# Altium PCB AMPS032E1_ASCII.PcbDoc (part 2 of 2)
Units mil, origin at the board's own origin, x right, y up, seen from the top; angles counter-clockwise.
Board outline 1650 x 2660 mil, 4 copper layers (Top Layer L1, GND Plane L2, VCC/VEE Plane L3, Bottom Layer L4), stack 61.6 mil thick; 53 components, 15 nets, 89 pads, 109 vias.
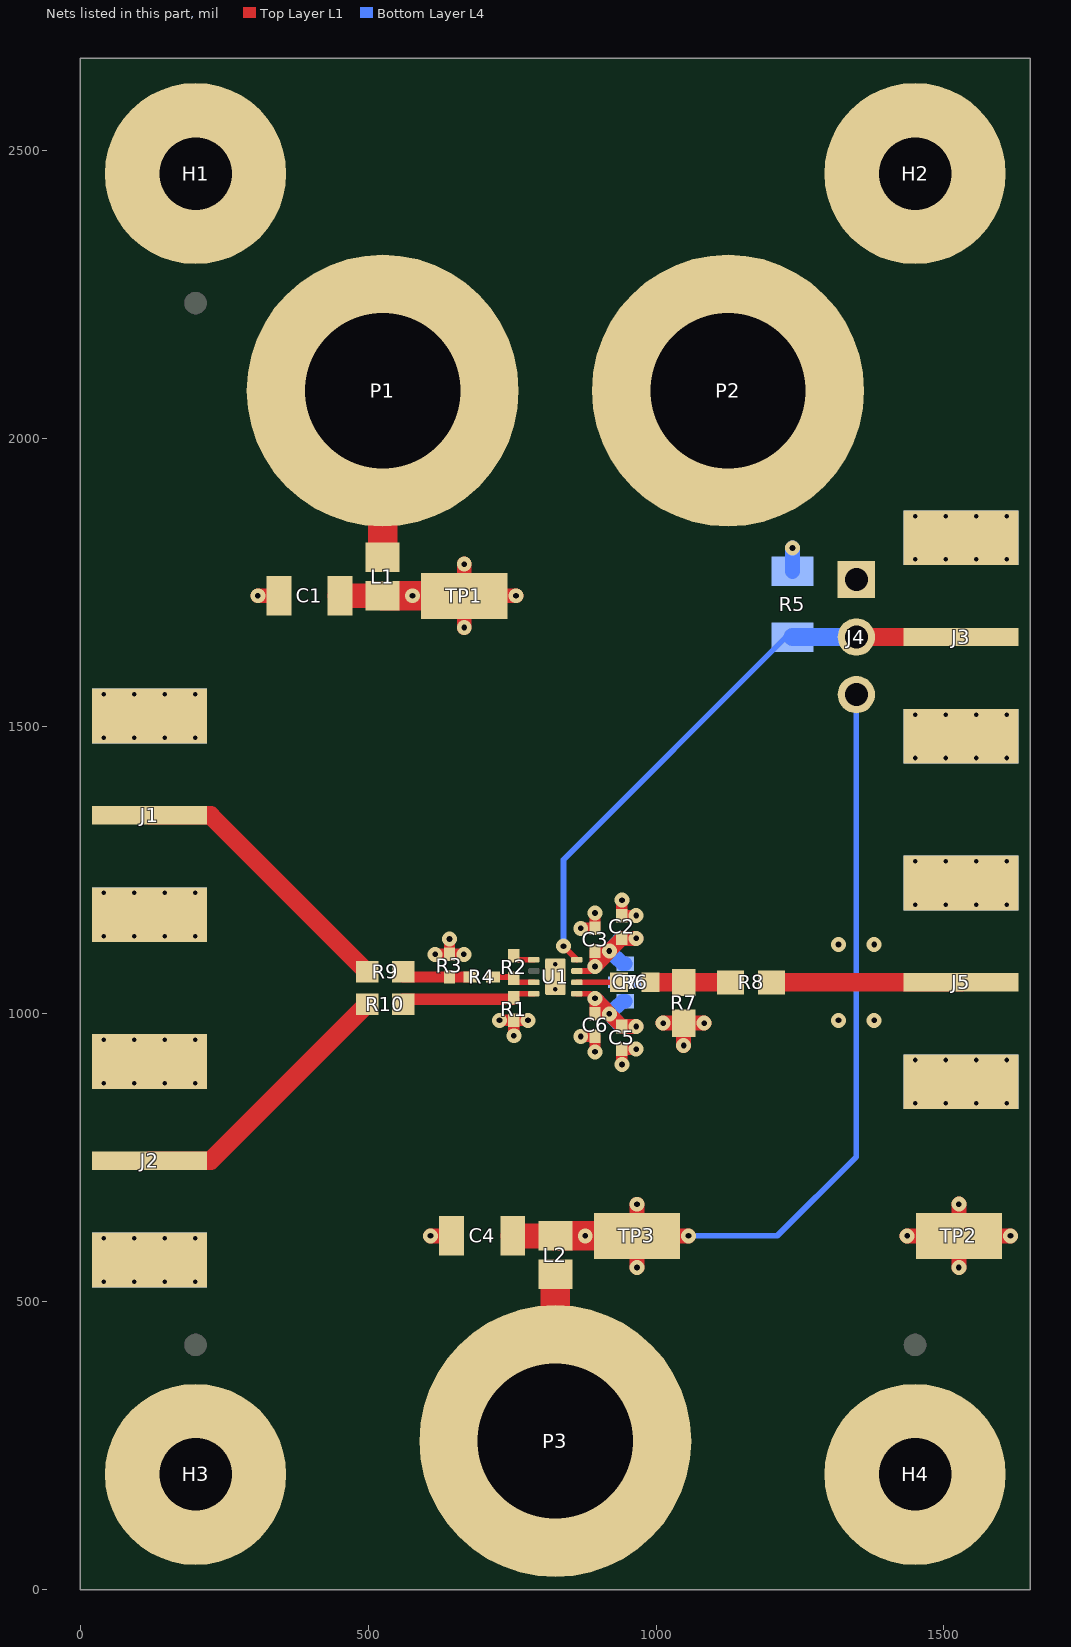
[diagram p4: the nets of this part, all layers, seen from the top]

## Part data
C1 C4: library part CMP-0008990-2, "CAP, CERM, 2.2 uF, 25 V, +/- 10%, X7R, 1206"
C2 C5: library part CMP-0006277-2, "CAP, CERM, 0.22 uF, 25 V, +/- 20%, X5R, 0402"
C3 C6: library part CMP-0006658-2, "CAP, CERM, 0.01 uF, 25 V, +/- 10%, X7R, 0402"
C7: library part CMP-0006820-2, "CAP, CERM, 0.01 uF, 50 V, +/- 20%, X7R, 0603"
FID1 FID2 FID3 FID4 FID5 FID6: "Fiducial mark.  There is nothing to buy or mount."
H1 H2 H3 H4: "Machine Screw, Round, #4-40 x 1/4, Nylon, Philips panhead"
H5 H6 H7 H8: "Standoff, Hex, 0.5\"L #4-40 Nylon"
J1 J2 J3 J5: library part CMP-0055822-1, "Connector, End launch SMA, 50 ohm, SMT"
J4: library part CMP-0075407-1, "Header, 100mil, 3x1, Gold, TH"
L1 L2: library part CMP-0003356-1, "Ferrite Bead, 1000 ohm @ 100 MHz, 0.5 A, 0805"
LBL1: library part THT-14-423-10, "Thermal Transfer Printable Labels, 0.650\" W x 0.200\" H - 10,000 per roll"
Logo1: library part TI_Logo, "Texas Instrument Corporate Signature"
Logo2: library part Pb-Free
Logo3: library part FCC_disclaimer, "FCC_disclaimer"
P1 P2 P3: library part CMP-0055169-2, "Standard Banana Jack, Uninsulated"
R1: library part CMP-0026404-1, "RES, 49.9, 1%, 0.063 W, 0402"
R2: library part CMP-0026366-1, "RES, 402, 1%, 0.063 W, 0402"
R3: library part CMP-0026822-2, "RES, 0, 5%, 0.063 W, 0402"
R4: library part CMP-0026503-1, "RES, 66.5, 1%, 0.063 W, 0402"
R5: library part CMP-0017019-2, "RES, 49.9, 1%, 0.25 W, 1206"
R6: library part CMP-0022078-3, "RES, 169, 1%, 0.1 W, 0603"
R7: library part CMP-0022582-2, "RES, 71.5, 1%, 0.1 W, 0603"
R8 R9 R10: library part CMP-0025697-2, "RES, 0, 5%, 0.1 W, 0603"
TP1 TP2 TP3: library part CMP-0055162-1, "Test Point, Miniature, SMT"
U1: library part CMP-0013445-3, "OPA852IDSG, DSG0008A (WSON-8)"
ZZ1: library part AssemblyNoteLabel
ZZ2 ZZ3 ZZ4: library part AssemblyNote

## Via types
v1: diameter 19.68, hole 7.87, Top Layer L1 to Bottom Layer L4, tented both sides, 64 vias
v2: diameter 26, hole 10, Top Layer L1 to Bottom Layer L4, tented both sides, 43 vias
v3: diameter 19.68, hole 7.87, Top Layer L1 to Bottom Layer L4, 2 vias

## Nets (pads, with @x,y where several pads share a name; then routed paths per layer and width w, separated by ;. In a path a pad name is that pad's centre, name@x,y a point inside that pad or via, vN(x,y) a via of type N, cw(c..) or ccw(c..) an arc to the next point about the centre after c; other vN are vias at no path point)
GND: C1.2 C2.2 C3.2 C4.1 C5.1 C6.1 C7.3 H1.1 H2.1 H3.1 H4.1 J1.2 J1.3 J1.4 J1.5 J2.2 J2.3 J2.4 J2.5 J3.2 J3.3 J3.4 J3.5 J5.2 J5.3 J5.4 J5.5 P2.1 R1.1 R3.1 R5.1 R7.1 TP2.1 | length 872.2
  Top Layer L1 w19.68: v2(616.31,1103.64) R3.1@641.12,1103.64 ; v2(641.12,1130.42) R3.1@641.12,1103.64 ; v2(665.93,1103.64) R3.1@641.12,1103.64 ; v2(728.07,988.9) R1.1@752.88,988.9 ; v2(752.88,962.12) R1.1@752.88,988.9 ; v2(777.69,988.9) R1.1@752.88,988.9 ; v2(869.19,960.93) C6.1@894,960.93 v2(894,934.15) ; v2(869.19,1148.76) C3.2@894,1148.76 v2(894,1175.53) ; v2(940.63,912.07) C5.1@940.63,938.84 v2(965.44,938.84) ; v2(940.63,1197.62) C2.2@940.63,1170.84 v2(965.44,1170.84)
  Top Layer L1 w26: v2(308.08,1726.53) C1.2@344.7,1726.53 ; v2(608.08,614.47) C4.1@644.7,614.47 ; v2(1012.36,983.98) R7.1@1048,983.98 ; v2(1048,945.39) R7.1@1048,983.98 ; v2(1083.64,983.98) R7.1@1048,983.98 ; v2(1436.23,614.47) TP2.1@1526,614.47 ; v2(1526,559.54) TP2.1@1526,614.47 ; v2(1526,669.39) TP2.1@1526,614.47 ; v2(1615.77,614.47) TP2.1@1526,614.47
  Bottom Layer L4 w26: R5.1@1237,1769.02 v2(1237,1809.57)
  other v1: 40.5,534.84 93.5,534.84 146.5,534.84 199.5,534.84 40.5,610.16 93.5,610.16 146.5,610.16 199.5,610.16 1450.5,844.68 1503.5,844.68 1556.5,844.68 1609.5,844.68 40.5,879.84 93.5,879.84 146.5,879.84 199.5,879.84 1450.5,920 1503.5,920 1556.5,920 1609.5,920 40.5,955.16 93.5,955.16 146.5,955.16 199.5,955.16 40.5,1134.84 93.5,1134.84 146.5,1134.84 199.5,1134.84 1450.5,1189.68 1503.5,1189.68 1556.5,1189.68 1609.5,1189.68 40.5,1210.16 93.5,1210.16 146.5,1210.16 199.5,1210.16 1450.5,1265 1503.5,1265 1556.5,1265 1609.5,1265 1450.5,1444.68 1503.5,1444.68 1556.5,1444.68 1609.5,1444.68 40.5,1479.84 93.5,1479.84 146.5,1479.84 199.5,1479.84 1450.5,1520 1503.5,1520 1556.5,1520 1609.5,1520 40.5,1555.16 93.5,1555.16 146.5,1555.16 199.5,1555.16 1450.5,1789.68 1503.5,1789.68 1556.5,1789.68 1609.5,1789.68 1450.5,1865 1503.5,1865 1556.5,1865 1609.5,1865
  other v2: 1317,989 1379,989 1317,1120.68 1379,1120.68
NetJ1_1: J1.1 R9.2 | length 490.6
  Top Layer L1 w32: J1.1@120,1345 226.14,1345 R9.2@498,1073.13
NetJ2_1: J2.1 R10.2 | length 490.6
  Top Layer L1 w32: J2.1@120,745 226.14,745 R10.2@498,1016.87
NetJ3_1: J3.1 J4.2 R5.2 U1.8 | length 1034.7
  Top Layer L1 w9.84: v2(839,1117.69) U1.8@862.44,1094.25
  Top Layer L1 w32: J4.2@1348,1654.84 J3.1@1530,1654.84
  Bottom Layer L4 w10: v2(839,1117.69) 839,1268 1225.84,1654.84 R5.2@1237,1654.84
  Bottom Layer L4 w32: R5.2@1237,1654.84 J4.2@1348,1654.84
NetJ5_1: J5.1 R8.2 | length 329.6
  Top Layer L1 w32: R8.2@1200.43,1054.84 J5.1@1530,1054.84
NetL1_1: L1.1 P1.1 | length 289.5
  Top Layer L1 w51.18: L1.1@525,1793.46 P1.1@525,2083
NetL2_1: L2.1 P3.1 | length 289.5
  Top Layer L1 w51.18: P3.1@825,258 L2.1@825,547.54
NetR1_2: R1.2 R10.1 U1.4 | length 238.3
  Top Layer L1 w9.84: R1.2@752.88,1028.27 759.77,1035.16 U1.4@787.6,1035.16
  Top Layer L1 w19.68: R10.1@561,1016.87 561,1025.73 R1.2@752.88,1025.73
NetR2_1: R2.1 R4.2 U1.3 | length 73.8
  Top Layer L1 w9.84: R4.2@716.69,1064.27 R2.1@752.88,1064.27 ; R2.1@752.88,1061.73 759.77,1054.84 U1.3@787.6,1054.84
NetR2_2: R2.2 U1.1 | length 37.6
  Top Layer L1 w9.84: R2.2@752.88,1101.1 759.77,1094.21 U1.1@787.6,1094.21
NetR3_2: R3.2 R4.1 R9.1 | length 125.2
  Top Layer L1 w19.68: R9.1@561,1073.13 561,1064.27 R3.2@641.12,1064.27 R4.1@677.32,1064.27
NetR6_1: R6.1 U1.6 | length 72.7
  Top Layer L1 w9.84: U1.6@862.4,1054.84 R6.1@935.15,1054.84
NetR6_2: R6.2 R7.2 R8.1 | length 139
  Top Layer L1 w32: R6.2@990.56,1054.84 R7.2@1048,1054.84 R8.1@1129.57,1054.84
VCC: C1.1 C2.1 C3.1 C7.2 J4.1 L1.2 TP1.1 U1.7 | length 723.1
  Top Layer L1 w9.84: U1.7@862.4,1074.53 885.92,1074.53 v2(894,1082.61)
  Top Layer L1 w19.68: v2(894,1082.61) C3.1@894,1109.39 v2(918.81,1109.39) ; C2.1@940.63,1131.2 C2.1@940.63,1131.47
  Top Layer L1 w26: v2(666.75,1671.61) TP1.1@666.75,1726.54 ; v2(666.75,1781.46) TP1.1@666.75,1726.54 ; v2(756.52,1726.54) TP1.1@666.75,1726.54 ; v2(894,1082.61) 907.35,1097.02 v2(918.81,1109.39) C2.1@940.63,1131.2 ; C2.1@940.63,1131.47 v2(965.44,1131.47)
  Top Layer L1 w43.31: C1.1@451,1726.53 L1.2@525,1726.54
  Top Layer L1 w51.18: L1.2@525,1726.54 TP1.1@666.75,1726.54
  Bottom Layer L4 w25.2: v2(918.81,1109.39) 941.76,1087.52 C7.2@946.5,1087.52
  Bottom Layer L4 w26: v2(894,1082.61) v2(918.81,1109.39) 938.31,1130.44 v2(965.44,1131.47)
  other v2: 576.98,1726.54
VEE: C4.2 C5.2 C6.2 C7.1 J4.3 L2.2 TP3.1 U1.5 U1.9@825,1064.68 | length 1874.4
  Top Layer L1 w9.84: U1.5@862.4,1035.16 885.92,1035.16 v2(894,1027.08)
  Top Layer L1 w19.68: v2(894,1027.08) C6.2@894,1000.3 v2(918.81,1000.3) ; C5.2@940.63,978.21 C5.2@940.63,978.48
  Top Layer L1 w26: v2(894,1027.08) 907.35,1012.67 v2(918.81,1000.3) C5.2@940.63,978.48 ; C5.2@940.63,978.21 v2(965.44,978.21) ; v2(966.75,559.54) TP3.1@966.75,614.46 ; v2(966.75,669.39) TP3.1@966.75,614.46 ; v2(1056.52,614.46) TP3.1@966.75,614.46
  Top Layer L1 w43.31: C4.2@751,614.47 L2.2@825,614.46
  Top Layer L1 w51.18: L2.2@825,614.46 TP3.1@966.75,614.46
  Bottom Layer L4 w10: v2(1056.52,614.46) 1210.46,614.46 1348,752 J4.3@1348,1554.84
  Bottom Layer L4 w25.2: v2(918.81,1000.3) 941.76,1022.17 C7.1@946.5,1022.17
  Bottom Layer L4 w26: v2(894,1027.08) v2(918.81,1000.3) 938.31,979.25 v2(965.44,978.21)
  other v2: 876.98,614.46
  other v3: 825,1043.03 825,1086.34
pads on no net: FID1.1 FID2.1 FID3.1 FID4.1 FID5.1 FID6.1 U1.2 U1.9@825,1046.97 U1.9@825,1082.4

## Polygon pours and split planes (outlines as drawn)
GND on Bottom Layer L4 "Bottom Layer L4-GND" (solid, remove dead copper, pour order 0): 20,20 20,2640 1630,2640 1630,20
GND on Top Layer L1 "Top Layer L1-GND" (solid, remove dead copper, pour order 2): 20,20 20,2640 1630,2640 1630,20
GND on GND Plane L2 (split plane): 1629.9,20.1 20.1,20.1 20.1,2639.9 1629.9,2639.9
VEE on VCC/VEE Plane L3 (split plane): 837.9,1054.84 838.29,1052.89 839.4,1051.24 841.05,1050.13 843,1049.74 847.87,1049.74 848.44,1048.38 849.56,1046.92 851.01,1045.8 852.71,1045.1 854.53,1044.86 914.69,1044.84 914.69,1033.11 956.19,1033.11 956.19,1049.74 1629.9,1049.74 1629.9,20.1 20.1,20.1 20.1,1039.9 807,1039.9 808.95,1040.29 810.6,1041.4 811.71,1043.05 812.1,1045 812.1,1106.03 837.9,1106.03
VCC on VCC/VEE Plane L3 (split plane): 1629.9,1059.94 956.19,1059.94 956.19,1076.57 914.69,1076.57 914.69,1064.85 854.53,1064.82 852.71,1064.58 851.01,1063.88 849.56,1062.76 848.44,1061.31 848.1,1060.48 848.1,1111.13 847.71,1113.08 846.61,1114.74 844.95,1115.84 843,1116.23 807,1116.23 805.05,1115.84 803.4,1114.74 802.29,1113.08 801.9,1111.13 801.9,1060.48 801.56,1061.31 800.44,1062.76 798.99,1063.88 797.29,1064.58 795.47,1064.82 787.79,1064.82 787.6,1064.85 767.72,1064.85 767.72,1078.54 738.04,1078.54 733.5,1079.12 699.87,1079.11 699.87,1050.1 20.1,1050.1 20.1,2639.9 1629.9,2639.9

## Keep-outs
Keep-Out Layer:
  text ".Layer_Name" at 577,-858.49 h60

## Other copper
Top Layer L1:
  text ".Layer_Name" at 577,-858.49 h60
Bottom Layer L4:
  text ".Layer_Name" at 577,-858.49 h60
GND Plane L2 (plane layer: these items are gaps in the copper):
  the board outline again, w40
  text ".Layer_Name" at 577,-858.49 h60
VCC/VEE Plane L3 (plane layer: these items are gaps in the copper):
  lines w10: 0,1045 807,1045 807,1111.13 843,1111.13 843,1054.84 1650,1054.84
  lines w40: 0,0 0,2660 1650,2660 1650,0 0,0
  text ".Layer_Name" at 577,-858.49 h60

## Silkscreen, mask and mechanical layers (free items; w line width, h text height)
Top Overlay:
  circle w10: c795.47,1133.13 r5
  text "HIGH" at 1133.41,1734.84 h40
  text "LOW" at 1166.41,1534.84 h40
  text "'.PRJ_Number'.PCB_Rev" at 275,432 h40
  text ".Layer_Name" at 577,-858.49 h60
Bottom Overlay:
  text ".Layer_Name" at 577,-858.49 h60
Top Paste:
  text ".Layer_Name" at 577,-858.49 h60
Bottom Paste:
  text ".Layer_Name" at 577,-858.49 h60
Top Solder:
  text ".Layer_Name" at 577,-858.49 h60
  text ".Layer_Name" at 577,-858.49 h60
Bottom Solder:
  text ".Layer_Name" at 577,-858.49 h60
Drill Guide:
  text ".Layer_Name" at 577,-858.49 h60
M1 Board Outline:
  the board outline again, w10
  text ".Layer_Name" at 577,-858.49 h60
M2 Board Dimensions:
  rectangle: 125,-400 500,-275
  rectangle: 0,-275 125,-150
  lines w7: 0,-275 1000,-275 ; 125,-400 125,-150 ; 250,-400 250,-150 ; 500,-400 500,-150 ; 750,-400 750,-150 ; 0,-400 0,-150 1000,-150 1000,-400 0,-400
  text ".Layer_Name" at 577,-858.49 h60
M3 3D STEP Top:
  text ".Layer_Name" at 577,-858.49 h60
M4 3D STEP Bottom:
  text ".Layer_Name" at 577,-858.49 h60
M5 Assembly Top:
  lines w10: -292,-930.17 6308,-930.17 ; -292,-726.83 6310,-726.83 ; -292,-523.5 -292,-1133.5 3713,-1133.5 6310,-1133.5 6310,-523.5 -291.5,-523.5 -291.5,-1133.5 1284,-1133.5 ; 2173,-1133.5 2173,-523.5 ; 3440,-726.83 3440,-523.5 ; 4280,-726.83 4280,-523.5 ; 4902,-1140 4902,-937.17
  text "COMPONENTS MARKED 'DNP' SHOULD NOT BE POPULATED." at 1153.5,-318.5 h60
  text "ASSEMBLY VARIANT:" at 1153,-434 h60
  text ".VariantName" at 2189,-434 h60
  text "PCB VIEWED FROM TOP SIDE" at -228.5,-655.67 h60
  text "BOARD #:" at 2248,-655.67 h60
  text ".PRJ_Number" at 2793.5,-655.67 h60
  text "REV:" at 3638,-655.67 h60
  text ".PCB_Rev" at 3929.5,-655.67 h60
  text "SVN REV:" at 4476,-655.67 h60
  text ".VersionControl_RevNumber" at 4982,-655.67 h60
  text "TID #:" at 2248,-859 h60
  text ".TID" at 2793.5,-859 h60
  text "PLOT NAME =" at -228.5,-1064.34 h60
  text ".plot_File_Name" at 577,-1064.34 h60
  text "GENERATED    :" at 2250,-1064.34 h60
  text ".Print_Date" at 3119.5,-1064.34 h60
  text ".Print_Time" at 3848.5,-1064.34 h60
  text "TEXAS INSTRUMENTS" at 5113,-1064.34 h60
M6 Assembly Bottom:
  lines w10: -292.5,-727.33 6309.5,-727.33 ; -290.5,-930.67 6309.5,-930.67 ; 1115.5,-1140.5 1115.5,-937.67 ; 1737.5,-727.33 1737.5,-524 ; 2577.5,-727.33 2577.5,-524 ; 3844.5,-1134 3844.5,-524 ; 4733.5,-1134 6309,-1134 6309,-524 -292.5,-524 -292.5,-1134 2304.5,-1134 6309.5,-1134 6309.5,-524
  text "COMPONENTS MARKED 'DNP' SHOULD NOT BE POPULATED." at 6102,-318 h60
  text ".VariantName" at 5058,-434 h60
  text "ASSEMBLY VARIANT:" at 6097,-434 h60
  text ".VersionControl_RevNumber" at 1035.5,-656.17 h60
  text "SVN REV:" at 1541.5,-656.17 h60
  text ".PCB_Rev" at 2088,-656.17 h60
  text "REV:" at 2379.5,-656.17 h60
  text ".PRJ_Number" at 3224,-656.17 h60
  text "BOARD #:" at 3769.5,-656.17 h60
  text "PCB VIEWED FROM BOTTOM SIDE" at 6246,-656.17 h60
  text ".TID" at 3224,-859.5 h60
  text "TID #:" at 3769.5,-859.5 h60
  text "TEXAS INSTRUMENTS" at 904.5,-1064.84 h60
  text ".Print_Time" at 2169,-1064.84 h60
  text ".Print_Date" at 2898,-1064.84 h60
  text "GENERATED    :" at 3767.5,-1064.84 h60
  text ".plot_File_Name" at 5440.5,-1064.84 h60
  text "PLOT NAME =" at 6246,-1064.84 h60
M9 Title Sheet:
  lines w10: -491.5,1041.5 -291.5,1041.5 ; -491.5,3416.5 -291.5,3416.5 ; -491.5,5791.5 -291.5,5791.5 ; 2008.5,-1333.5 2008.5,-1133.5 ; 2008.5,7966.5 2008.5,8166.5 ; 4508.5,-1333.5 4508.5,-1133.5 ; 4508.5,7966.5 4508.5,8166.5 ; 6321,-1133.5 6321,-523.5 11303.5,-523.5 ; 7008.5,-1333.5 7008.5,-1133.5 ; 7008.5,7966.5 7008.5,8166.5 ; 9508.5,-1333.5 9508.5,-1133.5 ; 9508.5,7966.5 9508.5,8166.5 ; 11303.5,-1133.5 11303.5,-523.5 ; 11303.5,-823.5 14303.5,-823.5 ; 11303.5,-223.5 14303.5,-223.5 ; 11304.5,370.5 14304.5,370.5 ; 12008.5,-1333.5 12008.5,-1133.5 ; 12008.5,7966.5 12008.5,8166.5 ; 12808.5,-1123.5 12808.5,-523.5 ; 14303.5,-523.5 11303.5,-523.5 ; 14303.5,76.5 11303.5,76.5 ; 14308.5,66.5 14308.5,-1133.5 ; 14308.5,871 11304.5,871 11303.5,871 11303.5,370.5 11303.5,76.5 ; 14308.5,1041.5 14508.5,1041.5 ; 14308.5,3416.5 14508.5,3416.5 ; 14308.5,5791.5 14508.5,5791.5 ; 11303.5,-523.5 11303.5,76.5 ; 14308.5,-1133.5 -291.5,-1133.5 -291.5,7966.5 14308.5,7966.5 14308.5,-1133.5 ; -491.5,-1333.5 14508.5,-1333.5 14508.5,8166.5 -491.5,8166.5 -491.5,-1333.5
  text "1" at 739.84,8036.5 h70
  text "2" at 3235.5,8036.5 h70
  text "3" at 5724.84,8036.5 h70
  text "4" at 8231.51,8036.5 h70
  text "5" at 10730.5,8036.5 h70
  text "6" at 13235.5,8036.5 h70
  text "A" at -416.5,6893.5 h70
  text "A" at 14383.5,6893.5 h70
  text "B" at -416.5,4513.5 h70
  text "B" at 14383.5,4513.5 h70
  text "C" at -416.5,2138.5 h70
  text "C" at 14383.5,2138.5 h70
  text "PROJECT TITLE:" at 11343.5,277.5 h45
  text ".PRJ_Title" at 11393.5,144.17 h70
  text "DESIGNED FOR:" at 11343.5,-23.5 h45
  text ".PRJ_Customer" at 11393.5,-163.5 h70
  text "D" at -416.5,-231.5 h70
  text "D" at 14383.5,-231.5 h70
  text "FILE NAME:" at 11343.5,-323.5 h45
  text ".PCB_File_Name_No_Path" at 11393.5,-443.5 h70
  text "Texas Instruments (TI) and/or its licensors do not warrant the accuracy or completeness of this specification" at 6374,-605.34 h45
  text "ENGINEER:" at 11343.5,-613.5 h45
  text "LAYOUT BY:" at 12848.5,-613.5 h45
  text "or any information contained therein. TI and/or its licensors do not warrant that this design will meet" at 6329.01,-718 h45
  text ".PRJ_Engineer" at 11393.5,-768.49 h70
  text ".PCB_Layout" at 12899,-768.49 h70
  text "the specifications, will be suitable for your application or fit for any particular purpose, or will operate in" at 6329.01,-830.67 h45
  text ".Layer_Name" at 577,-858.49 h60
  text "ALTIUM DESIGNER VERSION:" at 12848.5,-923.5 h45
  text "an implementation. TI and/or its licensors do not warrant that the design is production worthy. You should" at 6329.01,-943.33 h45
  text "completely validate and test your design implementation to confirm the system functionality for your application." at 6374,-1056 h45
  text ".print_Scale" at 11393.5,-1056.83 h70
  text ".Application_BuildNumber" at 12899,-1056.83 h70
  text "1" at 739.84,-1263.5 h70
  text "2" at 3235.5,-1263.5 h70
  text "3" at 5724.84,-1263.5 h70
  text "4" at 8231.51,-1263.5 h70
  text "5" at 10730.5,-1263.5 h70
  text "6" at 13235.5,-1263.5 h70
M10 Fab Notes:
  drawing of 173 lines, arcs and shapes, not listed
  text "DESIGN INFORMATION" at 12378.02,6201 h60
  text "MIN. TRACK WIDTH:" at 11733.46,6021 h60
  text "8" at 12829.7,6021 h60
  text "MIL" at 12984.46,6021 h60
  text "MIN. CLEARANCE:" at 11733.46,5889 h60
  text "0.2" at 12769.7,5889 h60
  text "mm" at 12984.46,5889 h60
  text "MIN. VIA PAD SIZE:" at 11733.46,5757 h60
  text "24" at 12799.71,5757 h60
  text "MIL" at 12984.46,5757 h60
  text "0.05mm (2MIL)" at 12428.46,5615.29 h60
  text "MINIMUM ANNULAR RING" at 11404.23,5611 h60
  text "EXTERNAL" at 13136.46,5611 h60
  text "PER" at 11604.23,5493 h60
  text "IPC-D-275 CLASS 2 LEVEL C" at 11824.23,5493 h60
  text "MIL, HOLES" at 13312.46,5380.71 h60
  text "+/-" at 12920,5380 h60
  text "+/-" at 13774,5380 h60
  text "REGISTRATION TOLERANCES:" at 11404.23,5375 h60
  text "METAL" at 12604,5375 h60
  text "5" at 13180.2,5375 h60
  text "3" at 14013.2,5375 h60
  text "MIL" at 14129.46,5375 h60
  text "+/-" at 13774,5262 h60
  text "HOLE SIZE TOLERANCE (UNLESS OTHERWISE SPECIFIED):" at 11404.23,5257 h60
  text "3" at 14013.2,5257 h60
  text "MIL" at 14129.46,5257 h60
  text "MATERIAL:" at 11329.46,5047.54 h60
  text "FR-4 High Tg" at 12315.9,4907.21 h60
  text "FR-408" at 11750.46,4898.64 h60
  text "OTHER" at 13238.46,4898.64 h60
  text "X" at 11602,4895 h60
  text "X" at 12161,4895 h60
  text "62 MIL (1.6mm) +/-10%" at 12070.56,4735.92 h60
  text "THICKNESS:" at 11404.23,4731.64 h60
  text "X" at 11942.4,4731.64 h60
  text "OTHER" at 13355.46,4731.64 h60
  text "TOLERANCE:" at 11404.23,4573.64 h60
  text "X" at 12243.53,4573.64 h60
  text "ANSI IPC-6012 TYPE 3 CLASS 2" at 12430.48,4573.64 h60
  text "OTHER +/-" at 12430.46,4417.64 h60
  text "BOW & TWIST:" at 11404.23,4260.64 h60
  text "X" at 12243.53,4260.64 h60
  text "ANSI IPC-6012 TYPE 3 CLASS 2" at 12430.48,4260.64 h60
  text "OTHER +/-" at 12430.46,4102.13 h60
  text "DRILLING:" at 11329.46,3963.64 h60
  text "REFERENCE:" at 11404.23,3846.64 h60
  text "X" at 12052.46,3846.64 h60
  text "AS SHOWN" at 12239.46,3846.64 h60
  text "X" at 12953.46,3846.64 h60
  text "NC_DRILL FILES" at 13090.46,3846.64 h60
  text "PTH COPPER THICKNESS:" at 11404.23,3688.64 h60
  text "X" at 12534.46,3688.64 h60
  text "20-30 um" at 12671.46,3688.64 h60
  text "OTHER" at 13388.46,3688.64 h60
  text "BOARD FINISH:" at 11329.46,3529.64 h60
  text "SILKSCREEN:" at 11484.68,3411.64 h60
  text "X" at 12433.46,3411.64 h60
  text "TOP" at 12559.46,3411.64 h60
  text "X" at 12943.46,3411.64 h60
  text "BOTTOM" at 13070.46,3411.64 h60
  text "SILKSCREEN COLOR:" at 11484.68,3244.64 h60
  text "X" at 12432.42,3244.64 h60
  text "WHITE" at 12559.46,3244.64 h60
  text "OTHER" at 13070.46,3244.64 h60
  text "X" at 12563.42,3085.44 h60
  text "GREEN" at 12690.46,3085.44 h60
  text "OTHER" at 13308.46,3085.44 h60
  text "SOLDER RESIST COLOR:" at 11484.68,3074.64 h60
  text "X" at 12563.42,2915.44 h60
  text "MATTE" at 12690.46,2915.44 h60
  text "SEMI-GLOSS" at 13308,2914.8 h60
  text "IMMERSION GOLD (ENIG)" at 12390.46,2726.92 h60
  text "ENEPIG" at 13728,2723.64 h60
  text "SURFACE FINISH:" at 11329.46,2722.64 h60
  text "X" at 12203.51,2722.64 h60
  text "IMM. TIN/SILVER OR EQUIV" at 11659,2565.64 h60
  text "OTHER" at 13090.46,2565.64 h60
  text "ARRAY/PANEL:" at 11329.46,2386.64 h60
  text "CUT AND TRIM PER M1 BOARD OUTLINE" at 12390.46,2382.35 h60
  text "N.C. ROUTE" at 12390.46,2230.64 h60
  text "X" at 13069.46,2230.64 h60
  text "V. SCORE" at 13256.46,2230.64 h60
  text "CERTIFICATION:" at 11329.46,2093.64 h60
  text "MATERIALS AND WORKMANSHIP FOR ALL PCBS" at 12054.46,2093.64 h60
  text "TO MEET OR EXCEED THE REQUIREMENTS OF:" at 12054.46,1995.64 h60
  text "X" at 11680.96,1859.13 h60
  text "ANSI IPC-A-600F CLASS ->" at 11819.96,1859.13 h60
  text "X" at 13459.02,1859.13 h60
  text "2" at 13577.96,1859.14 h60
  text "1" at 13262.96,1857.64 h60
  text "3" at 13931.96,1857.64 h60
  text "X" at 12495.02,1699.64 h60
  text "RoHS" at 12631.96,1699.64 h60
  text "OTHER" at 13276.36,1699.64 h60
  text "PER ORDER" at 13673.42,1699.64 h60
  text "ALL BOARDS MUST MEET OR EXCEED UL94-V0 REQUIREMENTS." at 11357,1534 h60
  text "PCB MUST BEAR THE UL94V-0 UL REGISTERED MATERIAL ID NUMBER" at 11357,1414 h60
  text "ADDITIONAL REQUIREMENTS:" at 11329.46,1240.64 h60
  text "32 Mil Traces on the Top Layer L1 to be 50 Ohm" at 2715,1169 h100
  text "MICROSECTION:" at 11404.23,1125.64 h60
  text "YES" at 12309.96,1125.64 h60
  text "REQUIRED" at 13171.46,969.49 h60
  text "BARE BOARD ELEC. TEST:" at 11404.23,966.64 h60
  text "NONE" at 12709.96,966.64 h60
  text "X" at 13044.46,966.64 h60
  text "PER ORDER" at 13763.46,966.64 h60
  text ".Layer_Name" at 577,-858.49 h60
M11 Gerber Information:
  lines w10: -292,-930.17 6308,-930.17 ; -292,-726.83 6310,-726.83 ; -292,-523.5 -292,-1133.5 3713,-1133.5 6310,-1133.5 6310,-523.5 -291.5,-523.5 -291.5,-1133.5 1284,-1133.5 ; 2173,-1133.5 2173,-523.5 ; 3440,-726.83 3440,-523.5 ; 4280,-726.83 4280,-523.5 ; 4902,-1140 4902,-937.17
  text "ALL ARTWORK VIEWED FROM TOP SIDE" at -228.5,-655.67 h60
  text "BOARD #:" at 2248,-655.67 h60
  text ".PRJ_Number" at 2793.5,-655.67 h60
  text "REV:" at 3638,-655.67 h60
  text ".PCB_Rev" at 3929.5,-655.67 h60
  text "SVN REV:" at 4476,-655.67 h60
  text ".VersionControl_RevNumber" at 4982,-655.67 h60
  text "LAYER NAME =" at -228.5,-858.49 h60
  text "TID #:" at 2248,-859 h60
  text ".TID" at 2793.5,-859 h60
  text "PLOT NAME =" at -228.5,-1064.34 h60
  text ".plot_File_Name" at 577,-1064.34 h60
  text "GENERATED    :" at 2250,-1064.34 h60
  text ".Print_Date" at 3119.5,-1064.34 h60
  text ".Print_Time" at 3848.5,-1064.34 h60
  text "TEXAS INSTRUMENTS" at 5113,-1064.34 h60
M12 Stackup:
  drawing of 295 lines, arcs and shapes, not listed
  text "Layer" at 9597.84,7807.5 h60
  text "Name" at 10007.76,7807.5 h60
  text "Material" at 11077.45,7807.5 h60
  text "Thickness" at 11937.22,7807.5 h60
  text "Constant" at 12587.06,7807.5 h60
  text "Board Layer Stack" at 13156.92,7807.5 h60
  text "1" at 9597.84,7687.5 h60
  text "Top Overlay" at 10007.76,7687.5 h60
  text "2" at 9597.84,7567.5 h60
  text "Top Solder" at 10007.76,7567.5 h60
  text "Solder Resist" at 11077.45,7567.5 h60
  text "0.40mil" at 11937.22,7567.5 h60
  text "3.5" at 12587.06,7567.5 h60
  text "3" at 9597.84,7447.5 h60
  text "Top Layer L1" at 10007.76,7447.5 h60
  text "Copper" at 11077.45,7447.5 h60
  text "1.40mil" at 11937.22,7447.5 h60
  text "4" at 9597.84,7327.5 h60
  text "Dielectric 1" at 10007.76,7327.5 h60
  text "FR408HR" at 11077.45,7327.5 h60
  text "15.00mil" at 11937.22,7327.5 h60
  text "3.8" at 12587.06,7327.5 h60
  text "5" at 9597.84,7207.5 h60
  text "GND Plane L2" at 10007.76,7207.5 h60
  text "Copper" at 11077.45,7207.5 h60
  text "1.40mil" at 11937.22,7207.5 h60
  text "6" at 9597.84,7087.5 h60
  text "Dielectric 2" at 10007.76,7087.5 h60
  text "FR-4 High Tg" at 11077.45,7087.5 h60
  text "26.00mil" at 11937.22,7087.5 h60
  text "4.6" at 12587.06,7087.5 h60
  text "7" at 9597.84,6967.5 h60
  text "VCC/VEE Plane L3" at 10007.76,6967.5 h60
  text "Copper" at 11077.45,6967.5 h60
  text "1.40mil" at 11937.22,6967.5 h60
  text "8" at 9597.84,6847.5 h60
  text "Dielectric 3" at 10007.76,6847.5 h60
  text "FR-4 High Tg" at 11077.45,6847.5 h60
  text "15.00mil" at 11937.22,6847.5 h60
  text "4.6" at 12587.06,6847.5 h60
  text "9" at 9597.84,6727.5 h60
  text "Bottom Layer L4" at 10007.76,6727.5 h60
  text "Copper" at 11077.45,6727.5 h60
  text "1.40mil" at 11937.22,6727.5 h60
  text "10" at 9597.84,6607.5 h60
  text "Bottom Solder" at 10007.76,6607.5 h60
  text "Solder Resist" at 11077.45,6607.5 h60
  text "0.40mil" at 11937.22,6607.5 h60
  text "3.5" at 12587.06,6607.5 h60
  text "11" at 9597.84,6487.5 h60
  text "Bottom Overlay" at 10007.76,6487.5 h60
  text ".Layer_Name" at 577,-858.49 h60
M13 Component Bodies Top:
  text ".Layer_Name" at 577,-858.49 h60
M14 Component Bodies Bottom:
  text ".Layer_Name" at 577,-858.49 h60
M15 Courtyards Top:
  text ".Layer_Name" at 577,-858.49 h60
M16 Courtyards Bottom:
  text ".Layer_Name" at 577,-858.49 h60
Drill Drawing:
  circle w10: c2583.82,442.52 r27.67
  lines w10: 2556.16,290.35 2611.49,290.35 2611.49,345.68 2556.16,345.68 2556.16,290.35 ; 2556.16,594.68 2611.49,594.68 2583.82,539.35 2556.16,594.68 ; 2556.16,691.52 2583.82,663.85 2611.49,691.52 2583.82,719.18 2556.16,691.52 ; 2556.16,788.35 2556.16,802.18 2569.99,816.02 2556.16,829.85 2556.16,843.68 2569.99,843.68 2583.82,829.85 2597.66,843.68 2611.49,843.68 2611.49,829.85 2597.66,816.02 2611.49,802.18 2611.49,788.35 2597.66,788.35 2583.82,802.18 2569.99,788.35 2556.16,788.35
  lines w12: 2506,253 5891.34,253 ; 2506,875.5 5891.34,875.5 ; 2844.01,128.5 2844.01,1000 ; 3176.17,128.5 3176.17,1000 ; 3812.65,128.5 3812.65,1000 ; 4071.85,128.5 4071.85,1000 ; 4447.09,128.5 4447.09,1000 ; 5324.79,128.5 5324.79,1000 ; 2506,128.5 5891.34,128.5 5891.34,1000 2506,1000 2506,128.5
  text "Symbol" at 2580.7,912.85 h72
  text "Quantity" at 2881.36,912.85 h72
  text "Finished Hole Size" at 3213.52,912.85 h72
  text "Plated" at 3850,912.85 h72
  text "Hole Type" at 4109.2,912.85 h72
  text "Drill Layer Pair" at 4484.44,912.85 h72
  text "Hole Tolerance" at 5362.14,912.85 h72
  text "66" at 2881.36,788.35 h60
  text "7.87mil (0.200mm)" at 3213.52,788.35 h60
  text "PTH" at 3850,788.35 h60
  text "Round" at 4109.2,788.35 h60
  text "Top Layer L1 - Bottom Layer L4" at 4484.44,788.35 h60
  text "43" at 2881.36,663.85 h60
  text "10.00mil (0.254mm)" at 3213.52,663.85 h60
  text "PTH" at 3850,663.85 h60
  text "Round" at 4109.2,663.85 h60
  text "Top Layer L1 - Bottom Layer L4" at 4484.44,663.85 h60
  text "3" at 2881.36,539.35 h60
  text "40.00mil (1.016mm)" at 3213.52,539.35 h60
  text "PTH" at 3850,539.35 h60
  text "Round" at 4109.2,539.35 h60
  text "Top Layer L1 - Bottom Layer L4" at 4484.44,539.35 h60
  text "4" at 2881.36,414.85 h60
  text "125.98mil (3.200mm)" at 3213.52,414.85 h60
  text "PTH" at 3850,414.85 h60
  text "Round" at 4109.2,414.85 h60
  text "Top Layer L1 - Bottom Layer L4" at 4484.44,414.85 h60
  text "3" at 2881.36,290.35 h60
  text "270.00mil (6.858mm)" at 3213.52,290.35 h60
  text "PTH" at 3850,290.35 h60
  text "Round" at 4109.2,290.35 h60
  text "Top Layer L1 - Bottom Layer L4" at 4484.44,290.35 h60
  text "119 Total" at 2881.36,165.85 h60
  text ".Layer_Name" at 577,-858.49 h60
M17 Embedded Cavity:
  text ".Layer_Name" at 577,-858.49 h60
M18 Embedded Assembly:
  text ".Layer_Name" at 577,-858.49 h60
M19 Embedded Keepout:
  text ".Layer_Name" at 577,-858.49 h60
